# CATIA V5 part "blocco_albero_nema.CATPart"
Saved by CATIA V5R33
Part number: blocco_albero_nema
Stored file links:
  C:\Users\Ryzen5700u\Desktop\robot_cicloidale_singolo\Assieme_robot_cicloidale_singolo\blocco_albero_nema.CATPart

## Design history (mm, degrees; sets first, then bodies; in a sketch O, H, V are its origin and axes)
Body1 "Solido1" (main body)
  Solid1: solid without history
